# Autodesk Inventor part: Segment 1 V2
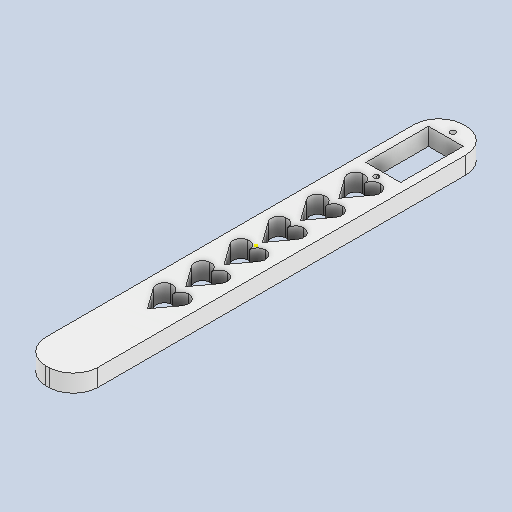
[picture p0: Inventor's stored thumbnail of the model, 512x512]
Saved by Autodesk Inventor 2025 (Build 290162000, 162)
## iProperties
Created: 2024-10
Part Number: Segment 1 V2
Material: ABS Plastic
Document SubType Name: Modeling
Designer: Braidyn
Density: 1.06 g/cm^3
Appearance: Smooth - White
Author: Braidyn
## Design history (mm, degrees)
sketch "Sketch1"
  geometry: L1 (-9.525, 76.2)-(9.525, 76.2); L2 (9.525, 76.2)-(9.525, -76.2); L3 (9.525, -76.2)-(-9.525, -76.2); L4 (-9.525, -76.2)-(-9.525, 76.2); L5 (-9.525, 76.2)-(9.525, -76.2); L6 (9.525, 76.2)-(-9.525, -76.2); 1 further point
  constraints: 12 end point, 2 midpoint, 2 parallel, 1 horizontal, 1 perpendicular
  dimensions: "d0" = 19.05 distance of L2.end L3.end; "d1" = 152.4 distance of L1.end L2.end
extrude "Extrusion1" new body sketch "Sketch1" distance "d2" = 6.35; taper "d3" = 0 deg
sketch "Sketch2"
  geometry: L1 (9.525, 76.2)-(-9.525, 76.2) reference; L2 (0, 76.2)-(-9.525, 76.2); L3 (-9.525, 76.2)-(-9.525, 66.675); L4 (9.525, -76.2)-(9.525, 76.2) reference; L5 (9.525, -76.2)-(9.525, -66.675); L6 (9.525, -66.675)-(-9.525, -66.675); L7 (-9.525, -76.2)-(9.525, -76.2) reference; L8 (-9.525, -76.2)-(9.525, -76.2); L9 (9.525, -76.2)-(9.525, 76.2); L10 (9.525, 76.2)-(-9.525, 76.2); L11 (-9.525, 76.2)-(-9.525, -76.2); L12 (-9.525, -76.2)-(9.525, 76.2); L13 (9.525, -76.2)-(-9.525, 76.2); A1 r 9.144 centre (-0.389, 67.064) between (0, 76.2) and (-9.525, 66.675); A2 r 9.144 centre (0.381, 67.064) between (9.525, 67.064) and (0, 76.2); A3 r 9.144 centre (0.389, -67.064) between (0, -76.2) and (9.525, -66.675); A4 r 9.144 centre (-0.389, -67.064) between (-9.525, -66.675) and (0, -76.2); 9 further points
  constraints: 20 end point, 8 point on circle, 4 centre point, 4 midpoint, 3 perpendicular, 3 point on line, 2 parallel, 1 collinear, 1 horizontal
  dimensions: "d4" = 9.525 distance of L1.end L3.end; "d5" = 9.144 radius of A1; "d6" = 9.144 radius of A2; "d7" = 9.525 distance of L4.start L5.end; "d8" = 9.144 radius of A3; "d9" = 9.144 radius of A4; "d10" = 152.4 distance of L9.end L8.end
extrude "Extrusion2" cut sketch "Sketch2" distance "d11" = 6.35; taper "d12" = 0 deg
sketch "Sketch4"
  geometry: L1 (0, 67.039)-(0, 51.799); L2 (0, 51.799)-(0, 36.559); L3 (0, 36.559)-(0, 21.319); L4 (-0.779, -76.2)-(0.779, -76.2) reference; L5 (0, -76.2)-(0, -38.1); L6 (0, 42.909)-(0, 36.559); L7 (0.052, 30.188)-(-5.572, 38.031); L8 (-5.572, 38.031)-(0.052, 30.188); L9 (5.557, 37.722)-(0.052, 30.188); L10 (0, 28.939)-(0, 22.589); L11 (0.052, 16.218)-(-5.572, 24.061); L12 (-5.572, 24.061)-(0.052, 16.218); L13 (5.557, 23.752)-(0.052, 16.218); L14 (0, 14.969)-(0, 8.619); L15 (0.052, 2.248)-(-5.572, 10.091); L16 (-5.572, 10.091)-(0.052, 2.248); L17 (5.557, 9.782)-(0.052, 2.248); L18 (0, 0.999)-(0, -5.351); L19 (0.052, -11.722)-(-5.572, -3.879); L20 (-5.572, -3.879)-(0.052, -11.722); L21 (5.557, -4.188)-(0.052, -11.722); L22 (0, -12.971)-(0, -19.321); L23 (0.052, -25.692)-(-5.572, -17.849); L24 (-5.572, -17.849)-(0.052, -25.692); L25 (5.557, -18.158)-(0.052, -25.692); L26 (0, -26.941)-(0, -33.291); L27 (0.052, -39.662)-(-5.572, -31.819); L28 (-5.572, -31.819)-(0.052, -39.662); L29 (5.557, -32.128)-(0.052, -39.662); C1 r 6.35 at (0, 67.039); A1 r 9.144 centre (-0.389, 67.064) between (-0.779, 76.2) and (-9.525, 67.454) reference; A2 r 2.839 centre (-3.15, 39.512) between (-3.549, 42.323) and (-5.572, 38.031); A3 r 2.891 centre (-2.891, 39.508) between (0, 39.508) and (-3.549, 42.323); A4 r 0.058 centre (0.056, 39.523) between (0, 39.508) and (0.112, 39.508); A5 r 3.052 centre (2.975, 39.349) between (5.557, 37.722) and (2.966, 42.402); A6 r 2.906 centre (2.906, 39.496) between (2.966, 42.402) and (0, 39.508); A7 r 2.906 centre (2.906, 25.526) between (2.966, 28.432) and (0, 25.538); A8 r 2.891 centre (-2.891, 25.538) between (0, 25.538) and (-3.549, 28.353); A9 r 0.058 centre (0.056, 25.553) between (0, 25.538) and (0.112, 25.538); A10 r 2.839 centre (-3.15, 25.542) between (-3.549, 28.353) and (-5.572, 24.061); A11 r 3.052 centre (2.975, 25.379) between (5.557, 23.752) and (2.966, 28.432); A12 r 2.906 centre (2.906, 11.556) between (2.966, 14.462) and (0, 11.568); A13 r 2.891 centre (-2.891, 11.568) between (0, 11.568) and (-3.549, 14.383); A14 r 0.058 centre (0.056, 11.583) between (0, 11.568) and (0.112, 11.568); A15 r 2.839 centre (-3.15, 11.572) between (-3.549, 14.383) and (-5.572, 10.091); A16 r 3.052 centre (2.975, 11.409) between (5.557, 9.782) and (2.966, 14.462); A17 r 2.906 centre (2.906, -2.414) between (2.966, 0.492) and (0, -2.402); A18 r 2.891 centre (-2.891, -2.402) between (0, -2.402) and (-3.549, 0.413); A19 r 0.058 centre (0.056, -2.387) between (0, -2.402) and (0.112, -2.402); A20 r 2.839 centre (-3.15, -2.398) between (-3.549, 0.413) and (-5.572, -3.879); A21 r 3.052 centre (2.975, -2.561) between (5.557, -4.188) and (2.966, 0.492); A22 r 2.906 centre (2.906, -16.384) between (2.966, -13.478) and (0, -16.372); A23 r 2.891 centre (-2.891, -16.372) between (0, -16.372) and (-3.549, -13.557); A24 r 0.058 centre (0.056, -16.357) between (0, -16.372) and (0.112, -16.372); A25 r 2.839 centre (-3.15, -16.368) between (-3.549, -13.557) and (-5.572, -17.849); A26 r 3.052 centre (2.975, -16.531) between (5.557, -18.158) and (2.966, -13.478); A27 r 2.906 centre (2.906, -30.354) between (2.966, -27.448) and (0, -30.342); A28 r 2.891 centre (-2.891, -30.342) between (0, -30.342) and (-3.549, -27.527); A29 r 0.058 centre (0.056, -30.327) between (0, -30.342) and (0.112, -30.342); A30 r 2.839 centre (-3.15, -30.338) between (-3.549, -27.527) and (-5.572, -31.819); A31 r 3.052 centre (2.975, -30.501) between (5.557, -32.128) and (2.966, -27.448); 6 further points
  constraints: 60 point on circle, 56 end point, 31 centre point, 9 point on line, 6 coincident, 3 vertical, 2 collinear, 1 midpoint, 1 tangent, 120 other
  dimensions: "d42" = 12.7 diameter of C1; "d43" = 15.24 distance of L1.start L1.end; "d44" = 15.24 distance of L1.end L2.end; "d45" = 15.24 distance of L2.end L3.end; "d48" = 38.1 distance of L5.start L5.end; "d58" = 13.97 distance of L6.start L10.start
extrude "Extrusion4" cut sketch "Sketch4" distance "d60" = 6.35; taper "d61" = 0 deg
sketch "Sketch6"
  geometry: L1 (0.762, 76.2)-(-0.779, 76.2) reference; L2 (-0.008, 76.2)-(0, 39.508); L3 (6.346, 46.424)-(-6.354, 46.424); L4 (-6.354, 46.424)-(-6.354, 69.284); L5 (-6.354, 69.284)-(6.346, 69.284); L6 (6.346, 69.284)-(6.346, 46.424); L7 (6.346, 46.424)-(-6.354, 69.284); L8 (-6.354, 46.424)-(6.346, 69.284); L9 (-0.004, 69.284)-(-0.007, 71.824); L10 (-0.004, 46.424)-(-0.001, 43.884); C1 r 0.953 at (-0.001, 43.884); C2 r 0.953 at (-0.007, 71.824); A1 r 2.906 centre (2.906, 39.496) between (2.966, 42.402) and (0, 39.508) reference; 4 further points
  constraints: 18 end point, 6 midpoint, 2 centre point, 2 coincident, 2 parallel, 2 point on line, 1 horizontal, 1 perpendicular
  dimensions: "d66" = 12.7 distance of L4.end L5.end; "d67" = 22.86 distance of L3.end L4.end; "d68" = 2.54 distance of L9.start L9.end; "d69" = 2.54 distance of L10.start L10.end; "d70" = 1.905 diameter of C1; "d71" = 1.905 diameter of C2
extrude "Extrusion5" cut sketch "Sketch6" distance "d72" = 25.4; taper "d73" = 0 deg
sketch "Sketch7"
  geometry: 1 further point
body "Solid1"
node "Sketch Rectangular Pattern2" dims "d55" = 25.4, "d58" = 13.97
other parameters: "sa_0" = 222411.08076
